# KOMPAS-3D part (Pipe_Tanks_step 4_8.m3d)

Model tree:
1. X Axis
2. Y Axis
3. Z Axis  (labels: Pipe Dn 150)
     Òîëùèíà ñòåíêè 1 = 1

Referenced files in C:\Documents and Settings\kashirsky\Мои документы\Camtasia Studio\Pipelines3D\Tanks\: Tanks_step 4.a3d
Referenced files in C:\Program Files\ASCON\KOMPAS-3D V10\Libs\Piping\LOAD\: Piping_C_Pipe_150_1000.m3d
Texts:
  Pipe Dn 150
  Steel ASTM A295
  Three Point Plane
  Plane at Angle
  Line and Point Plane
  Axis through Two Vertices
  Axis of Feature
  Axis of Conical Surface
  Axis through Edge
  Trim by Surface
  Trim by Sketch
  Feature with No History
  Intersection Axis of Two Planes
  Two Line Plane
  Line and Face Plane
  Bend by line
  Hole in sheet body
  Cut in sheet body
  Point in CM
  Linear Dimension from Line to Point
  Surface Finish Symbol
  Geometric Tolerance Symbol
  Leader #1
  Leader #2
  Leader #3
  Shape Deviations and Datum
  Node point number
  Mark of coordination axis
  Node point designation
  Mark/Reference designation with leader
  Mark/reference designation on line
  Mark/Reference designation without leader
  Plane of section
